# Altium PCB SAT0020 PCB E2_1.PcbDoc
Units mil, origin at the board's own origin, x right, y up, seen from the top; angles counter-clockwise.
Board outline 2000 x 1200 mil, 4 copper layers (Top Layer, GND, VCC, Bottom Layer), stack 90 mil thick; 48 components, 23 nets, 126 pads, 88 vias.
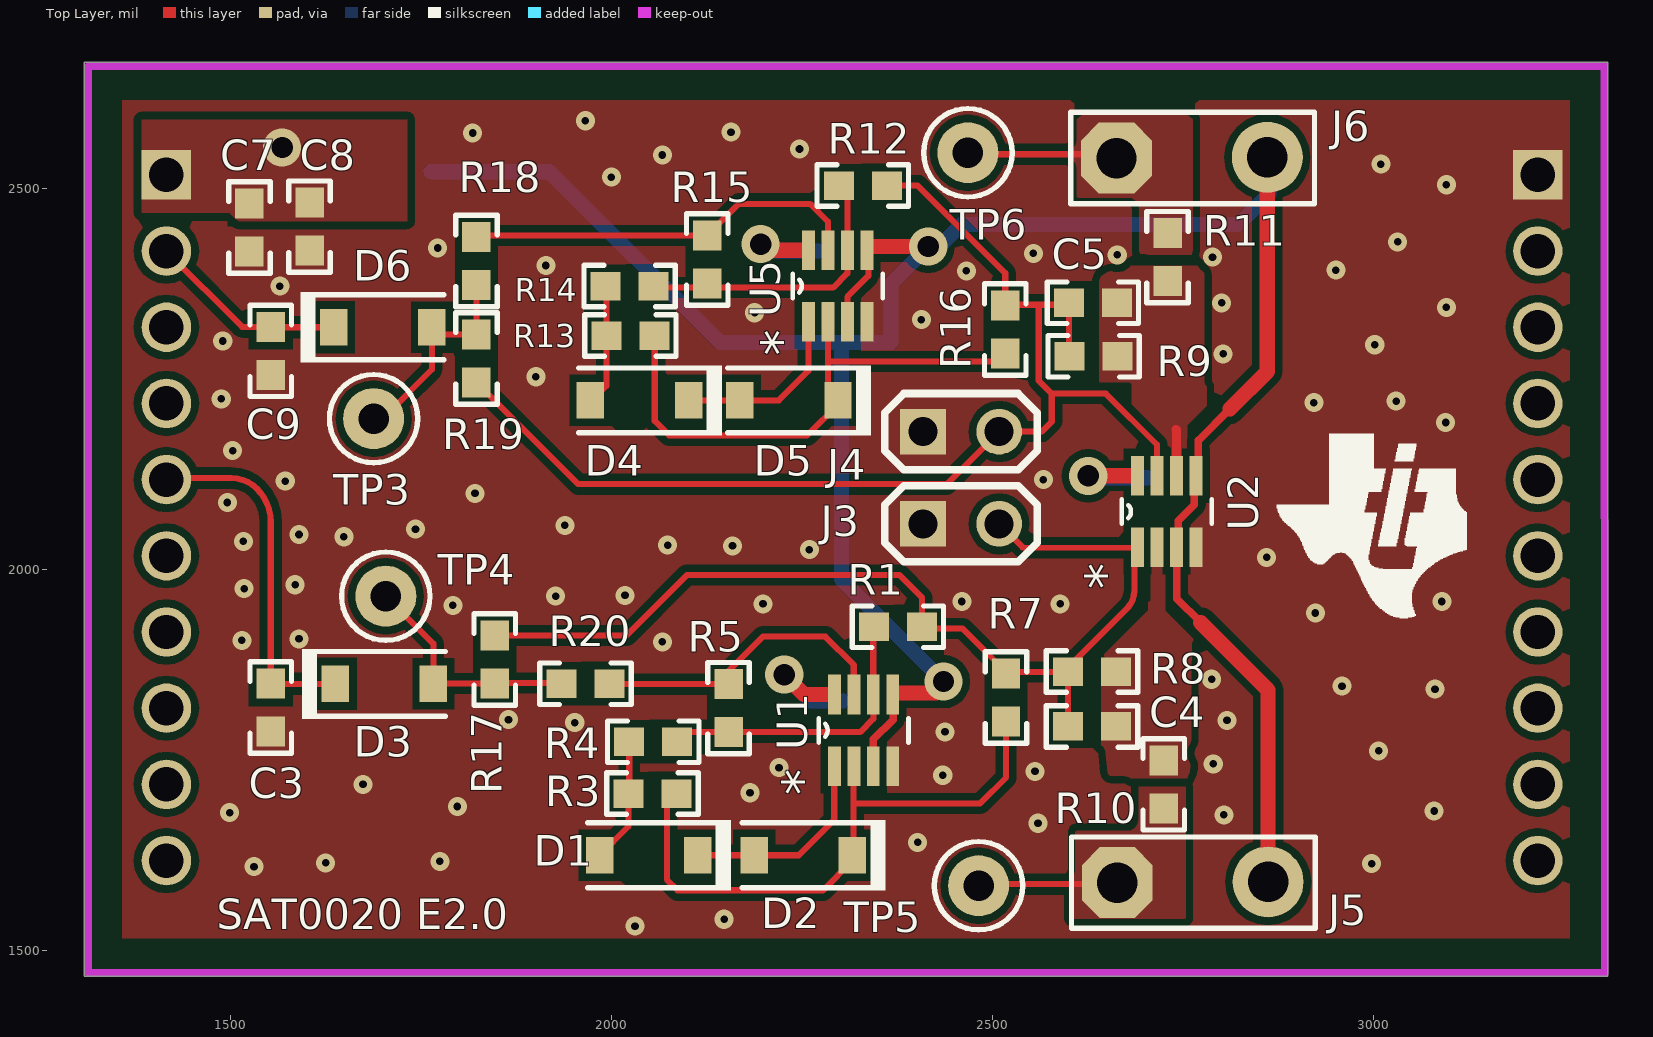
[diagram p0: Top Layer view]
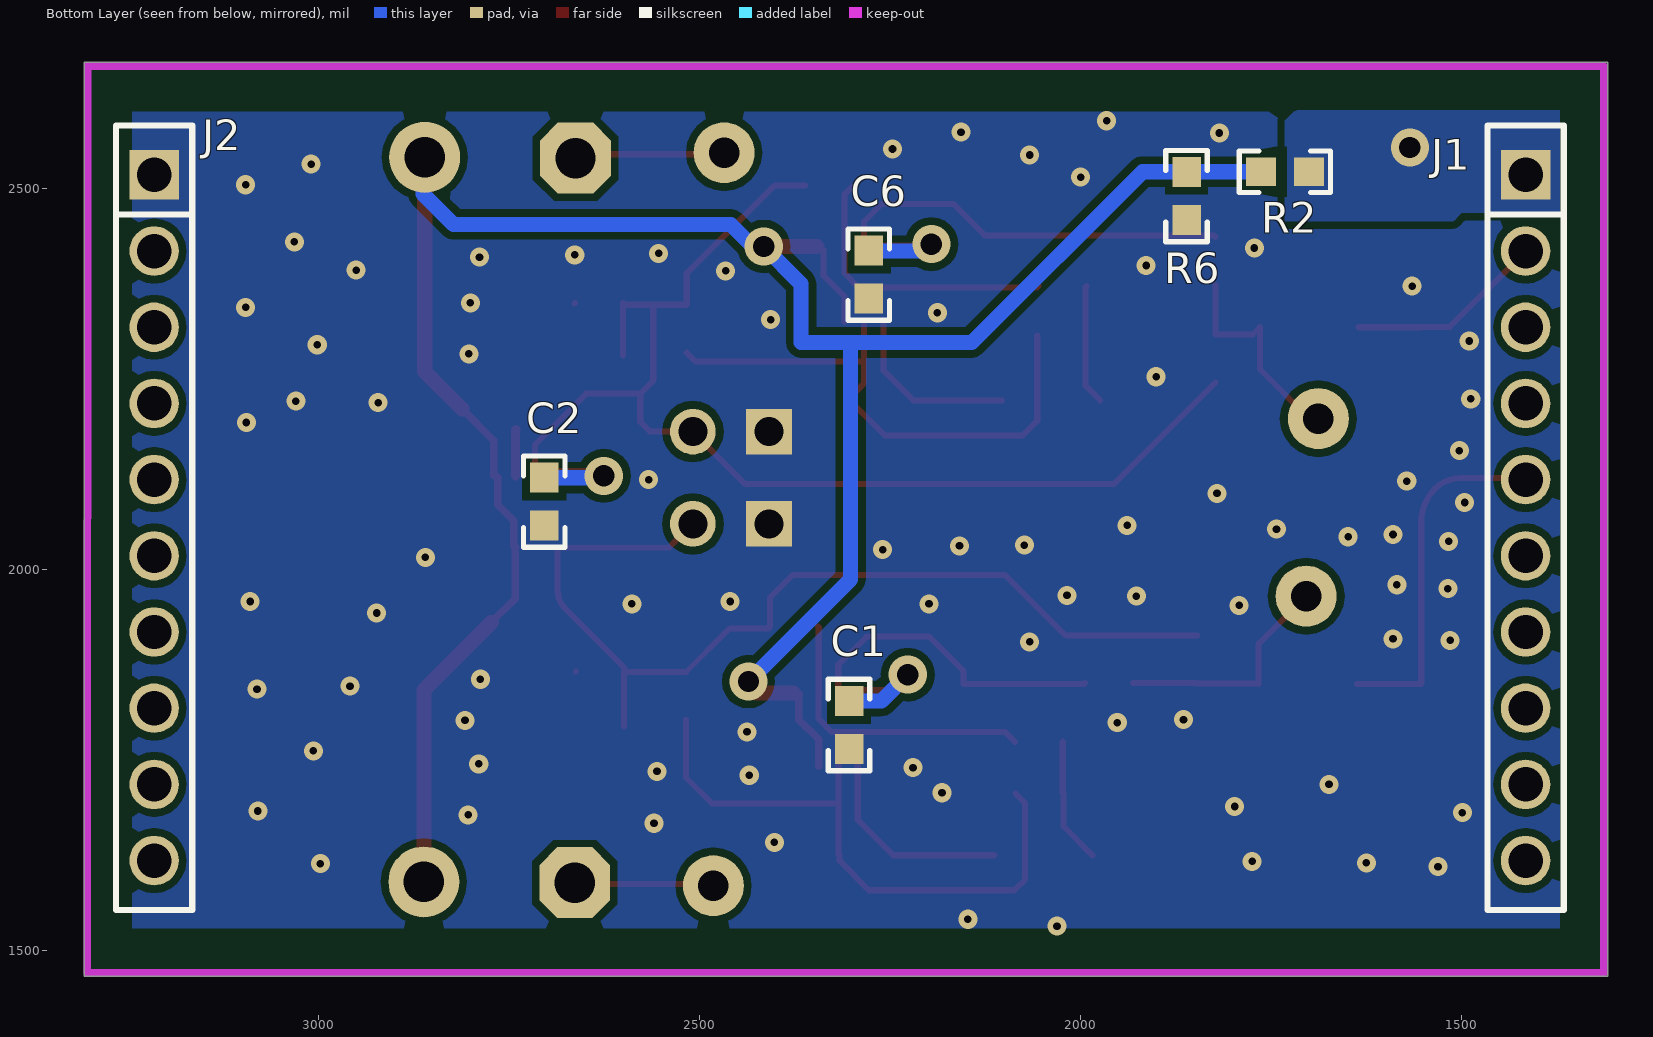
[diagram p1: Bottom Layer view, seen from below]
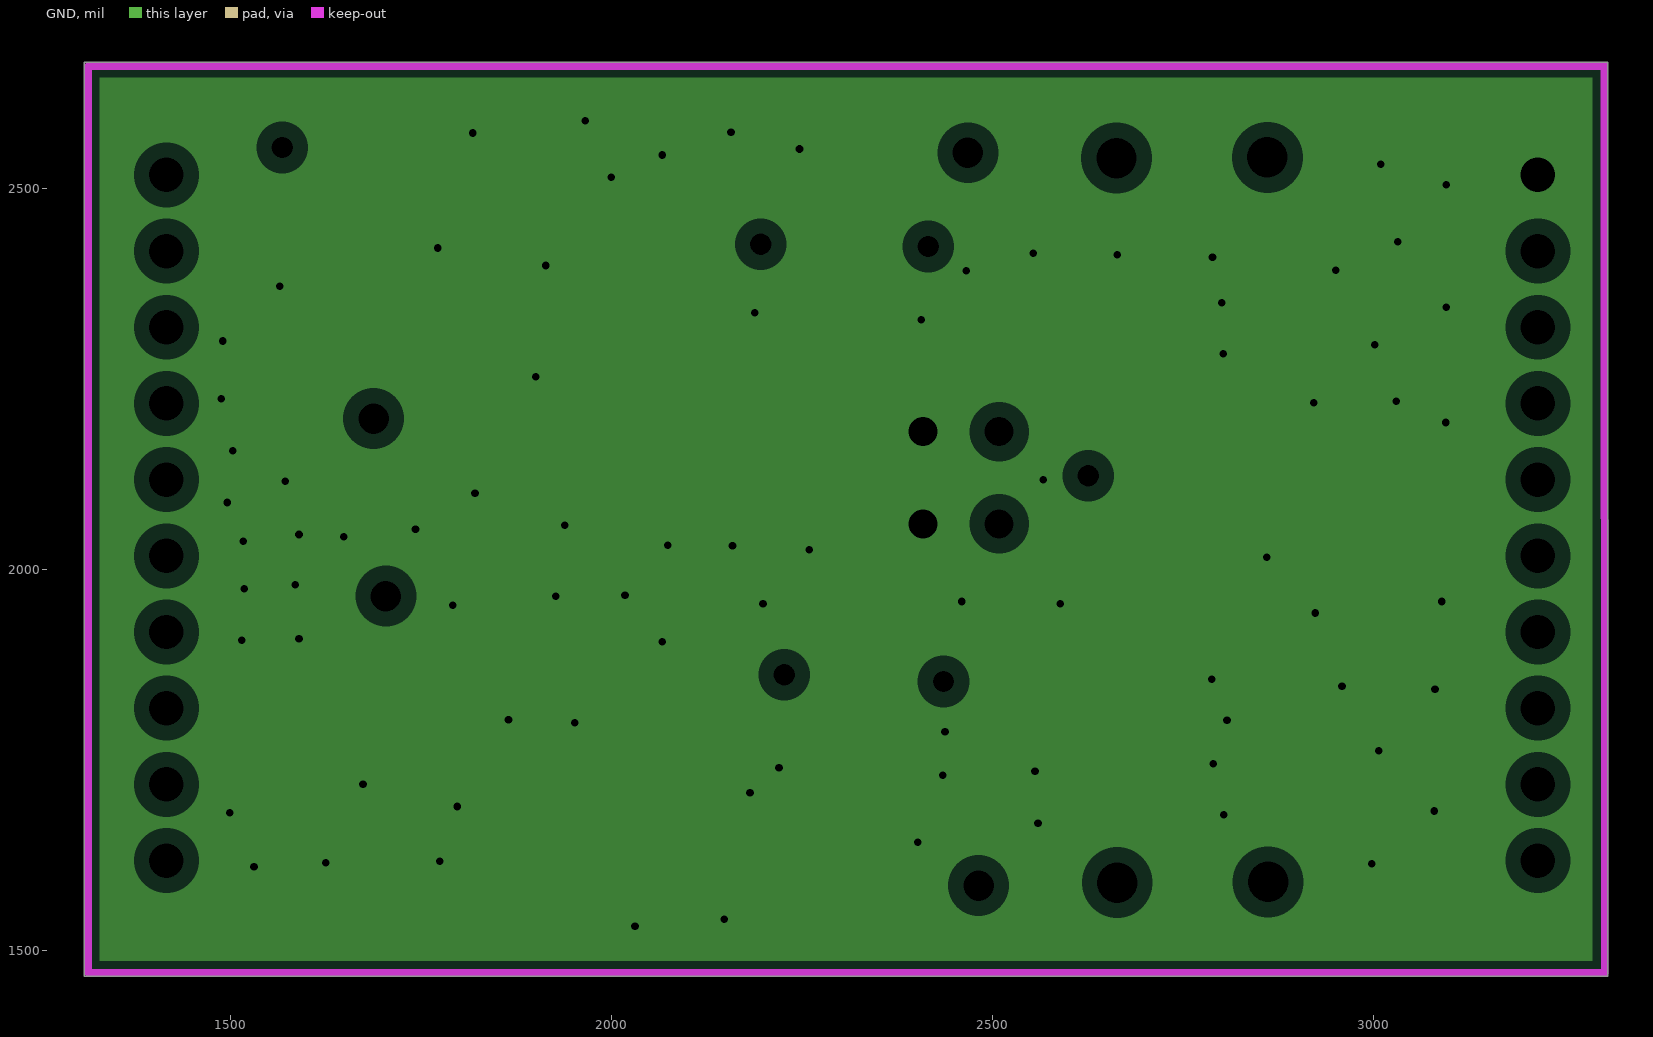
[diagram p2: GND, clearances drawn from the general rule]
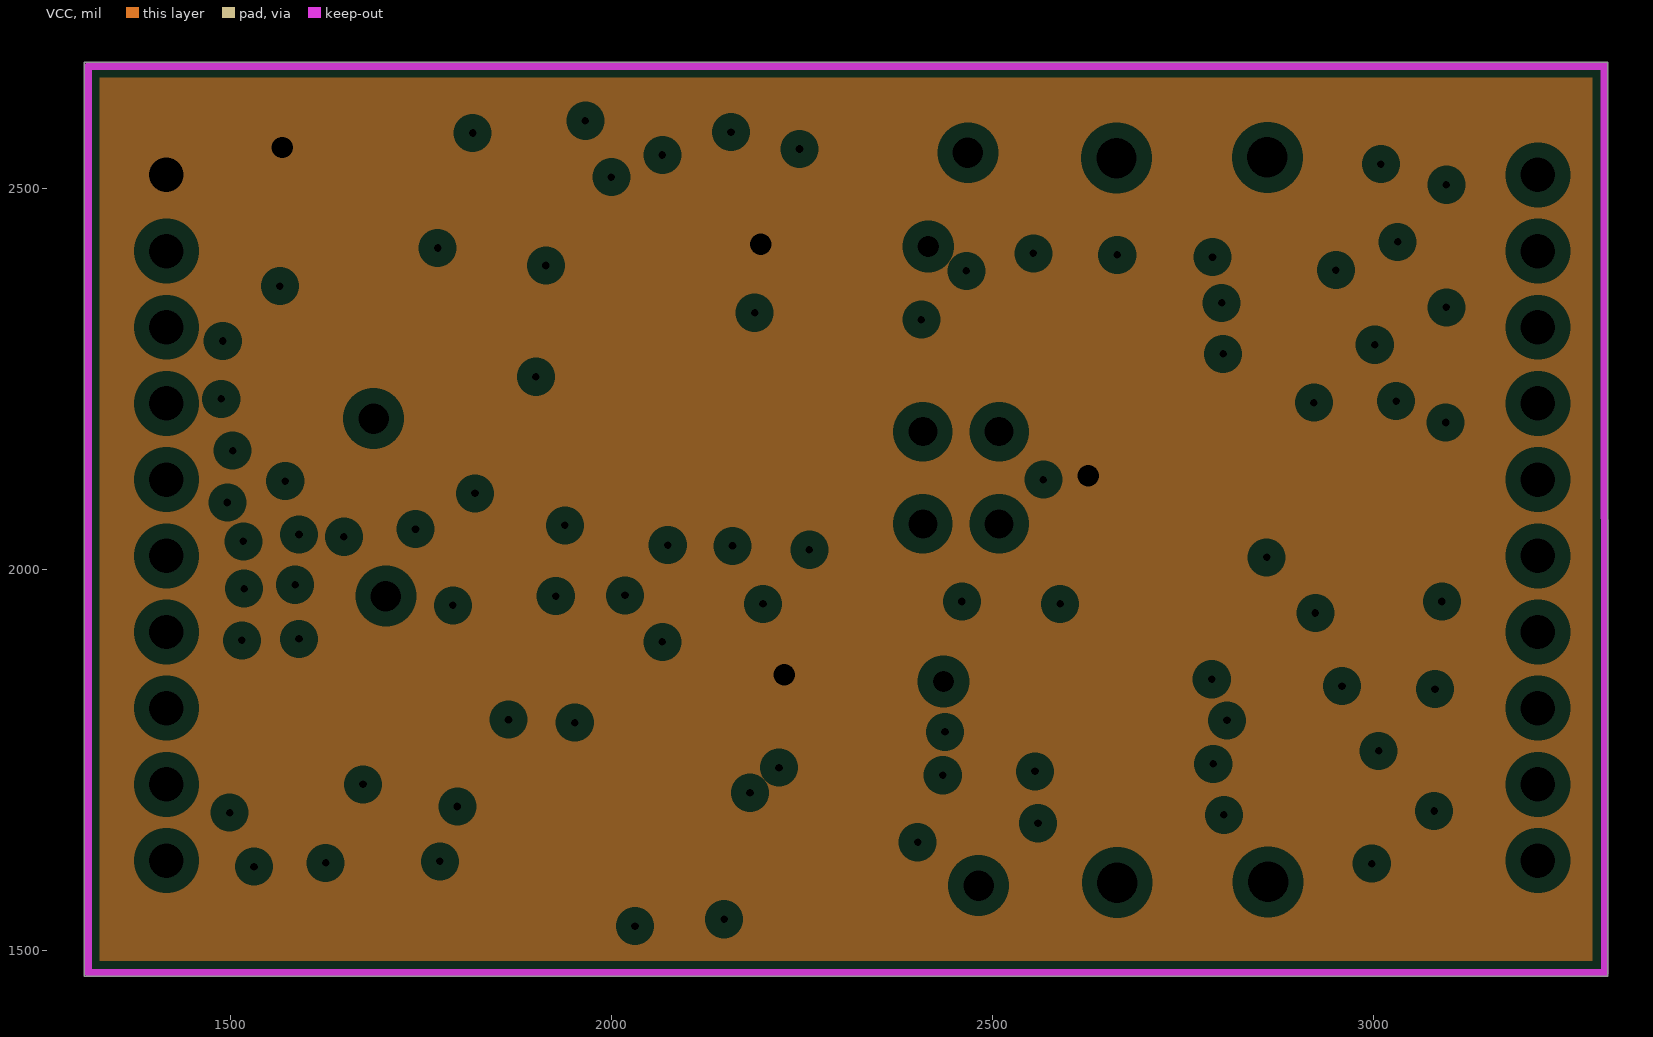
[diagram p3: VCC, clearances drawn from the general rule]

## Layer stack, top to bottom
Top Layer: signal copper 1.4
Dielectric: core 59.2, FR-4, Dk 4.8
GND: plane copper 1.4, net GND
Dielectric: prepreg 12.6, FR-4, Dk 4.8
VCC: plane copper 1.4, net VCC
Dielectric: core 12.6, FR-4, Dk 4.8
Bottom Layer: signal copper 1.4

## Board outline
1308,1466 3308,1466 3308,2666 1308,2666

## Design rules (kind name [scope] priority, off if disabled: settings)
AcuteAngle [All] p1: minimum=4.50000000000000E+0001 checktracksonly=FALSE
AssemblyTestPointUsage [All] p1: valid=2
Clearance [All] p1: gap=10
Clearance Clearance_BoardEdge_MountingHoles [OnCopper and InComponentClass('Mounting Holes') vs IsKeepOut] p2: gap=20
Clearance Clearance_BoardEdge_Poly [OnCopper and InPoly vs IsKeepOut] p3: gap=20
Clearance Clearance_BoardEdge [OnCopper and Not InComponentClass('Logo') and not InComponentClass('FiducialMark') and not InRegion(1000,500,4000,800) vs IsKeepOut] p4: gap=20
Clearance U1 [InComponent('U1')] p5: gap=8
Clearance U2 [InComponent('U2')] p6: gap=8
Clearance U5 [InComponent('U5')] p7: gap=8
ComponentClearance ComponentClearance_Logo [InComponentClass(Logo)] p1 off: gap=50 collisioncheckmode=3 verticalgap=10 showdistances=FALSE
ComponentClearance ComponentClearance_ScrewToNut [(HasFootprint('NY PMS 440 0025 PH')) vs (HasFootprint('Keystone_1902C'))] p2 off: gap=5 collisioncheckmode=3 verticalgap=10 showdistances=FALSE
ComponentClearance ComponentClearance_MountingHoles [InComponentClass('Mounting Holes')] p3 off: gap=250 collisioncheckmode=3 verticalgap=100000 showdistances=FALSE
ComponentClearance ComponentClearance_SmallPassives [HasFootprint('0201*') or HasFootprint('0402*') or HasFootprint('0508') or HasFootprint('0603*') or HasFootprint('0612') or HasFootprint('0805*') or HasFootprint('0815*') or HasFootprint('0830*') or HasFootprint('1206*') or HasFootprint('1210*') or HasFootprint('1808*') or HasFootprint('1812*') or HasFootprint('1825*') or HasFootprint('2010*') or HasFootprint('2220*') or HasFootprint('2225*') or HasFootprint('2512*') or HasFootprint('2728*') or HasFootprint('3518*') vs HasFootprint('0201*') or HasFootprint('0402*') or HasFootprint('0508') or HasFootprint('0603*') or HasFootprint('0612') or HasFootprint('0805*') or HasFootprint('0815*') or HasFootprint('0830*') or HasFootprint('1206*') or HasFootprint('1210*') or HasFootprint('1808*') or HasFootprint('1812*') or HasFootprint('1825*') or HasFootprint('2010*') or HasFootprint('2220*') or HasFootprint('2225*') or HasFootprint('2512*') or HasFootprint('2728*') or HasFootprint('3518*')] p4 off: gap=20 collisioncheckmode=3 verticalgap=10 showdistances=FALSE
ComponentClearance ComponentClearance_THtoSMT [IsThruComponent vs IsSMTComponent] p5 off: gap=100 collisioncheckmode=3 verticalgap=100000 showdistances=FALSE
ComponentClearance ComponentClearance_THtoTH [IsThruComponent vs IsThruComponent] p6 off: gap=118.11 collisioncheckmode=3 verticalgap=100000 showdistances=FALSE
ComponentClearance [All] p7: gap=5 collisioncheckmode=3 verticalgap=10 showdistances=FALSE
DiffPairsRouting [All] p1: maxlimit=100 minlimit=10 mostfreqgap=10 maxuncoupledlength=1000
FabricationTestPointUsage TestPointUsage [All] p1: valid=2 allowmultiple=FALSE
FabricationTestpoint Testpoint [All] p1: side=3 testpointundercomponent=TRUE minsize=40 maxsize=100 preferedsize=60 minholesize=0 maxholesize=40 preferedholesize=32 testpointgrid=1 allowsidetop=TRUE allowsidebottom=TRUE usegrid=TRUE gridtolerance=0.01
FanoutControl Fanout_LCC [IsLCC] p1: bgadir=Out bgaviamode=Centered fanoutstyle=Auto fanoutdirection=Alternating viagrid=1 // Fanout_LCC (Default Rule)
FanoutControl Fanout_BGA [IsBGA] p2: bgadir=Out bgaviamode=Centered fanoutstyle=Auto fanoutdirection=Alternating viagrid=1 // Fanout_BGA (Default Rule)
FanoutControl Fanout_Default [All] p4: bgadir=Out bgaviamode=Centered fanoutstyle=Auto fanoutdirection=Alternating viagrid=1 // Fanout_Default (Default Rule)
FanoutControl Fanout_Small [(CompPinCount < 5)] p5: bgadir=Out bgaviamode=Centered fanoutstyle=Auto fanoutdirection=OutThenIn viagrid=1 // Fanout_Small (Default Rule)
HoleSize [All] p1: absolutevalues=TRUE maxlimit=550 minlimit=5 maxpercent=80.000 minpercent=20.000
MinimumAnnularRing [All] p1: minimumring=8
MinimumSolderMaskSliver MinimumSolderMaskSliver_Logo [InComponentClass('Logo') vs InComponentClass('Logo')] p1: minsoldermaskwidth=0.7
MinimumSolderMaskSliver [All] p2: minsoldermaskwidth=5
PlaneClearance [All] p1: clearance=20
PlaneConnect [All] p1: planeconnectstyle=Direct reliefexpansion=10 reliefentries=4 reliefconductorwidth=10 reliefairgap=10
PolygonConnect [All] p1: connectstyle=Direct reliefconductorwidth=10 reliefentries=4 polygonreliefangle="90 Angle" airgapwidth=10
RoutingVias [All] p1: holewidth=10 width=25 viastyle="Through Hole" minholewidth=5 minwidth=20 maxholewidth=100 maxwidth=150
SMDToCorner [All] p1: distance=30000
SilkToSilkClearance [All] p1: silktosilkclearance=5
SilkscreenOverComponentPads [All] p1: minsilkscreentomaskgap=5
SolderMaskExpansion [All] p1: expansion=3
Width [All] p1: maxlimit=100 minlimit=6 preferedwidth=10 checkconnectedcopper=TRUE
13 further rules are at their usual default settings.

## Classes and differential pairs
component class Hardware_ANSI-B: !PCB

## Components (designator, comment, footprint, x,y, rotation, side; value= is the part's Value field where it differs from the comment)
C1 "06033C104KAT2A" 0603 2304,1796 r90 bottom
C2 "06033C104KAT2A" 0603 2704,2089 r270 bottom
C3 "C1608X5R0J105K" 0603 1553,1819 r270 top
C4 "C0603C681K5RACTU" 0603 2631,1794 r0 top
C5 "C0603C681K5RACTU" 0603 2632,2350 r0 top
C6 "06033C104KAT2A" 0603 2278,2387 r90 bottom
C7 "GRM188R60J106ME47D" 0603 1525,2449 r270 top
C8 "06033C104KAT2A" 0603 1604,2450 r90 top
C9 "C1608X5R0J105K" 0603 1553,2287 r270 top
D1 "1N4148W-7-F" SOD-123 2049,1625 r180 top
D2 "1N4148W-7-F" SOD-123 2252,1625 r180 top
D3 "1N4148W-7-F" SOD-123 1702,1850 r0 top
D4 "1N4148W-7-F" SOD-123 2037,2222 r180 top
D5 "1N4148W-7-F" SOD-123 2233,2222 r180 top
D6 "1N4148W-7-F" SOD-123 1700,2318 r0 top
J1 "SSW-110-23-F-S" CONN_SSW-110-23-F-S 1416,2518 r90 bottom
J2 "SSW-110-23-F-S" CONN_SSW-110-23-F-S 3216,2518 r90 bottom
J3 "HEADER_1X2" HDR100_1X2 2409,2060 r0 top
J4 "HEADER_1X2" HDR100_1X2 2409,2181 r0 top
J5 "DT_Sensor" DT_Sensor 2824,1449 r0 top
J6 "DT_Sensor" DT_Sensor 2823,2400 r0 top
R1 "CRCW0603100KFKEA" 0603 2376,1925 r180 top
R2 "CRCW060310K0JNEA" 0603 1732,2522 r180 bottom
R3 "CRCW0603100KFKEA" 0603 2054,1706 r180 top
R4 "CRCW060351K0JNEA" 0603 2055,1774 r0 top
R5 "CRCW0603100KFKEA" 0603 2154,1818 r90 top
R6 "CRCW060310K0JNEA" 0603 1861,2490 r90 bottom
R7 "CRCW0603100KFKEA" 0603 2518,1832 r270 top
R8 "CRCW0603200MJPEAHR" 0603 2631,1866 r180 top
R9 "CRCW0603200MJPEAHR" 0603 2633,2280 r180 top
R10 "CRCW060310K0JNEA" 0603 2725,1718 r270 top
R11 "CRCW060310K0JNEA" 0603 2730,2410 r270 top
R12 "CRCW0603100KFKEA" 0603 2330,2504 r180 top
R13 "CRCW0603100KFKEA" 0603 2025,2307 r180 top
R14 "CRCW060351K0JNEA" 0603 2024,2372 r0 top
R15 "CRCW0603100KFKEA" 0603 2126,2407 r90 top
R16 "CRCW0603100KFKEA" 0603 2517,2315 r270 top
R17 "CRCW06030000Z0EA" 0603 1847,1882 r270 top
R18 "CRCW06030000Z0EA" 0603 1823,2405 r90 top
R19 "CRCW06030000Z0EA" 0603 1823,2277 r90 top
R20 "CRCW06030000Z0EA" 0603 1966,1850 r0 top
TP3 "5002" Keystone5002 1688,2198 r90 top
TP4 "5002" Keystone5002 1704,1965 r90 top
TP5 "5002" Keystone5002 2482,1585 r0 top
TP6 "5002" Keystone5002 2468,2547 r0 top
U1 "OPA2337_DCN_8" DCN8 2331,1789 r90 top
U2 "OPA2337_DCN_8" DCN8 2729,2076 r90 top
U5 "OPA2337_DCN_8" DCN8 2297,2372 r90 top

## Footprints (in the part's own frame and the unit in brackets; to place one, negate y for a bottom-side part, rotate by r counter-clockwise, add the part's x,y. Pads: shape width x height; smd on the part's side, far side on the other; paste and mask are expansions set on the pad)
0603 [mm] "0603 from SM-752 data"
  rect 1x0.95 smd: 1(-0.8,0) 2(0.8,0)
  silkscreen extent -1.52,-0.69 1.52,0.69, body extent -0.87,-0.47 0.87,0.47, height 0.85
CONN_SSW-110-23-F-S [mm] "SAMTEC"
  rect 1.65x1.65 hole 1.15: 1(0,0)
  round 1.65 hole 1.15: 2(-2.54,0) 3(-5.08,0) 4(-7.62,0) 5(-10.16,0) 6(-12.7,0) 7(-15.24,0) 8(-17.78,0) 9(-20.32,0) 10(-22.86,0)
  silkscreen extent -24.51,-1.27 1.65,1.27, body extent -24.43,-1.27 1.57,1.27, height 8.59
DCN8 [mil]
  rect 52x17 smd: 1(-47,38.39) 2(-47,12.8) 3(-47,-12.8) 4(-47,-38.39) 5(47,-38.39) 6(47,-12.8) 7(47,12.8) 8(47,38.39)
  silkscreen extent -16,-59 16,59
DT_Sensor [mil]
  oct 93x93 hole 53: 1(-160,140)
  round 93 hole 53: 2(38,141)
  silkscreen extent -220,80 100,200
HDR100_1X2 [mil]
  rect 60x60 hole 38: 1(0,0)
  round 60 hole 38: 2(100,0)
  silkscreen extent -50,-50 150,50
Keystone5002 [mil] "For Keystone 500x miniature loop terminals"
  round 80 hole 40: 1(0,0)
  silkscreen extent -58,-58 58,58, body extent -49,-49 49,49, height 182
SOD-123 [mm] "On Semi recommended land pattern"
  rect 0.915x1.22 smd: 1(-1.637,0) 2(1.637,0)
  silkscreen extent -2.74,-1.17 2.03,1.17, body extent -1.93,-0.9 1.93,0.9, height 1.35

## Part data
C1 C2 C6 C8: "CAP, CERM, 0.1uF, 25V, +/-10%, X7R, 0603"
C3 C9: "CAP, CERM, 1uF, 6.3V, +/-10%, X5R, 0603"
C4 C5: "CAP, CERM, 680pF, 50V, +/-10%, X7R, 0603"
C7: "CAP, CERM, 10uF, 6.3V, +/-20%, X5R, 0603"
D1 D2 D3 D4 D5 D6: "Diode, Ultrafast, 100V, 0.15A, SOD-123"
J1 J2: "Connector, Receptacle, 100mil, 10x1, Gold plated, TH"
J3 J4: "Header, Male 2-pin, 100mil spacing,"
J5 J6: library part Component_1
R1 R3 R5 R7 R12 R13 R15 R16: "RES, 100k ohm, 1%, 0.1W, 0603"
R2 R6 R10 R11: "RES, 10k ohm, 5%, 0.1W, 0603"
R4 R14: "RES, 51k ohm, 5%, 0.1W, 0603"
R8 R9: library part CRCW0603200KJNEA, "RES, 200M ohm, 5%, 0.1W, 0603"
R17 R18 R19 R20: "RES, 0 ohm, 5%, 0.1W, 0603"
TP3 TP4 TP5 TP6: "Test Point, TH, Miniature, White"
U1 U2 U5: "Imported"

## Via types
v1: diameter 25, hole 10, Top Layer to Bottom Layer, 82 vias
v2: diameter 50, hole 28, Top Layer to Bottom Layer, 6 vias

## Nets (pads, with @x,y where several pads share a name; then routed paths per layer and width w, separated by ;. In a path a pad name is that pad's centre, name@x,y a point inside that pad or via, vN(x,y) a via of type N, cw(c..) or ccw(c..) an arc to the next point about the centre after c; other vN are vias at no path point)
GND: C1.1 C2.2 C3.2 C6.1 C7.2 C8.1 C9.2 J2.1 J3.1 J4.1 R6.1 U1.4 U2.4 U5.4
  other v1: 2031,1532 2148,1541 1531,1610 2998,1614 1625,1615 1775,1617 2402,1642 2560,1667 2804,1678 1499,1681 3080,1683 1798,1689 2182,1707 1674,1718 2435,1730 2556,1735 2220,1740 2790,1745 3007,1762 2438,1787 1952,1799 2808,1802 1865,1803 3081,1843 2959,1847 2788,1856 2067,1905 1515,1907 1590,1909 2924,1943 1792,1953 2199,1955 2589,1955 2460,1958 3090,1958 1927,1965 2018,1966 1518,1975 1585,1980 2860,2016 2260,2026 2159,2031 2074,2032 1517,2037 1649,2043 1590,2046 1743,2053 1939,2058 1496,2088 1821,2100 1572,2116 2567,2118 1503,2156 3095,2193 2922,2219 3030,2221 1488,2224 1901,2253 2803,2283 3002,2295 1490,2300 2407,2328 2188,2337 3096,2344 2801,2350 1565,2372 2466,2392 2951,2393 1914,2399 2789,2410 2664,2413 2554,2415 1772,2422 3032,2430 3096,2505 2000,2515 3010,2532 2067,2544 2247,2552 1818,2573 2157,2574 1966,2589
NetC4_1: C4.1 J3.2 R1.1 R7.1 R8.2 R17.1 U2.1 | length 1322
  Top Layer w8: R17.1 2019.95,1913.5 2099.19,1992.74 2378.26,1992.74 2407.5,1963.5 R1.1 2410,1922.5 2461,1922.5 2518,1865.5 2598,1865.5 R8.2@2598.5,1866 ; J3.2 2540,2029 2686.61,2028 2686.61,1970.09 ; C4.1 R8.2 R8.2@2598.5,1866 ; 2677.89,1950.41 ccw(c2658.3,1970) 2686,1970 ; 2679.5,1951.5 2598.5,1870.5 R8.2@2598.5,1866
NetC4_2: C4.2 R8.1 R10.1 U2.2 | length 0
NetC5_1: C5.1 J4.2 R9.2 R12.1 R16.1 R19.1 U2.7 | length 1609.8
  Top Layer w8: R19.1 1956.5,2112 2440,2112 J4.2 2565,2181 2578,2194 2578,2231 ; R12.1 2402,2504 2517,2389 2517,2347.5 2561,2347.5 ; R9.2@2600.5,2281 C5.1 2598,2347.5 2561,2347.5 ; U2.7 2716.2,2163.8 2649,2231 2578,2231 ; 2561,2347.5 2561,2248 2578,2231
NetC5_2: C5.2 R9.1 R11.2 U2.6 | length 62.7
  Top Layer w8: C5.2 C5.2@2664.5,2349
  Top Layer w12: 2741,2184 2741.8,2183.2 U2.6
NetD1_1: D1.1 D2.2 U1.1 | length 268.8
  Top Layer w8: D1.1 D2.2 2246,1625 2292.61,1671.61 U1.1
NetD1_2: D1.2 R3.2 R4.1 | length 165.1
  Top Layer w8: D1.2 2022.5,1662.97 R3.2 2023.5,1707 R4.1
NetD2_1: D2.1 R3.1 R7.2 U1.2 | length 798.5
  Top Layer w8: R3.1 2073,1693.5 2073,1593 2087,1579 2278,1579 2316.47,1617.47 D2.1 2318,1626.53 2318,1694.47 ; U1.2@2318,1741.8 2318,1694.47 ; R7.2@2518,1802.5 2518,1727 2484,1693 2319.47,1693 2318,1694.47
NetD3_2: D3.2 R17.2 R20.1 TP4.1 | length 306.3
  Top Layer w8: TP4.1 1766.47,1902.53 D3.2 1766.97,1850.5 R17.2 1847.5,1851 R20.1@1931.5,1851
NetD4_1: D4.1 D5.2 U5.1 | length 235.5
  Top Layer w8: D4.1@2103.47,2222 2170.53,2222 2220,2222 2258.61,2260.61 U5.1
NetD4_2: D4.2 R13.2 R14.1 | length 158.3
  Top Layer w8: D4.2@1974.53,2222 1993.5,2240.97 R13.2 1993.5,2371 R14.1
NetD5_1: D5.1 R13.1 R16.2 U5.2 | length 733.5
  Top Layer w8: R13.1 2057,2306.5 2057,2195 2076,2176 2257,2176 2299.47,2218.47 2299.47,2222 2303,2225.53 2284.2,2244.33 2284.2,2273 ; U5.2 2284.2,2273 ; R16.2@2517,2284.5 2505.5,2273 2284.2,2273
NetD6_2: D6.2 R18.1 R19.2 TP3.1 | length 286.1
  Top Layer w8: TP3.1 1699.94,2198 1764.47,2262.53 D6.2 1773.97,2308.5 R19.2 R18.1
NetJ5_1: J5.1 R10.2 TP5.1 | length 180.1
  Top Layer w8: TP5.1@2482,1587 2659.99,1587 J5.1@2661.5,1588.5
NetJ6_1: J6.1 R11.1 TP6.1 | length 172.1
  Top Layer w8: TP6.1@2495,2545 2665,2545 J6.1@2663.5,2543.5
NetR1_2: R1.2 R4.2 R5.1 U1.6 | length 391.4
  Top Layer w8: R4.2 2099,1786.5 2326.63,1786.5 2344,1803.87 2344,1835.8 U1.6 2343.8,1924.29 R1.2
NetR5_2: R5.2 R20.2 U1.7 | length 414.7
  Top Layer w8: R20.2@1994.5,1851 1996,1849.5 R5.2 2154,1867 2199,1912 2281,1912 2318.2,1874.8 U1.7
NetR12_2: R12.2 R14.2 R15.1 U5.6 | length 382.8
  Top Layer w8: R14.2 2057.5,2370 2291,2370 2309.8,2388.8 U5.6 2309.8,2492.71 R12.2
NetR15_2: R15.2 R18.2 U5.7 | length 526.6
  Top Layer w8: R18.2 1825,2438.5 R15.2 2167.5,2480 2261,2480 2284.2,2456.8 U5.7
VCC: C1.2 C2.1 C6.2 C7.1 C8.2 J1.1 R2.2 U1.8 U2.8 U5.8 | length 450.7
  Top Layer w20: v2(2196,2427) 2204,2419 U5.8@2255.7,2419 ; v2(2227,1862) 2253,1836 U1.8@2289.7,1836 ; v2(2626,2123) U2.8@2687.7,2123
  Bottom Layer w20: v2@2196,2418 2277.5,2418 C6.2 ; v2(2227,1862) 2261.5,1827.5 C1.2 ; v2(2626,2123) 2628.5,2120.5 C2.1
  other v2: 1568,2554
VCCDIV2: J5.2 J6.2 R2.1 R6.2 U1.3 U1.5 U2.3 U2.5 U5.3 U5.5 | length 3275.4
  Top Layer w8: U5.3 2309.8,2357.8 2337.3,2385.3 U5.5@2337.3,2419
  Top Layer w10: U1.3 2344,1742.2 2344,1777 2370,1803 2370,1835.39 U1.5 ; U2.5 2765.3,2120.91 2765.3,2085.3 2743.89,2063.89 2743.89,2031.09 U2.3 2742.2,2028.59 2742.2,1961.8 2773.5,1930.5 ; U2.5@2770.3,2123 2770.3,2169.3 2812,2211
  Top Layer w20: 2346,2424 v2(2416,2424) ; U1.5@2376.89,1838 v2@2426.5,1838 ; v2@2425,1842 v2(2436,1853) ; 2773.5,1930.5 2862,1842 J5.2 ; 2812,2211 2861,2260 J6.2
  Bottom Layer w20: R2.1 1919,2522 2143,2298 2367,2298 2367,2375 v2(2416,2424) v2@2416,2409.75 ; 2302,2297 2302,1987 v2(2436,1853) ; v2@2423.12,2416.88 2459.25,2453 2823,2453 2863,2493 J6.2@2863,2546
"VOUT 1": C3.1 D3.1 J1.5 | length 476.8
  Top Layer w8: J1.5@1407,2120 1501.2,2120 cw(c1501.2,2072.2) 1535,2106 cw(c1491.54,2062.54) 1553,2062.54 C3.1 1553.5,1850 D3.1
"VOUT 2": C9.1 D6.1 J1.2 | length 261
  Top Layer w8: J1.2 1515.5,2318.5 C9.1 1553.5,2318 D6.1
pads on no net: J1.3 J1.4 J1.6 J1.7 J1.8 J1.9 J1.10 J2.2 J2.3 J2.4 J2.5 J2.6 J2.7 J2.8 J2.9 J2.10

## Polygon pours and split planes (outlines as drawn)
GND on Bottom Layer "GND-BL" (solid, remove dead copper, pour order 24): 1371.25,2602.75 1371.25,1529.25 3244.75,1529.25 3244.75,2600.85 1373.15,2600.85 1371.25,2602.75
VCC on Bottom Layer "Vcc-In-BL" (solid, pour order 22): 1371.25,2602.75 1371.25,2469.25 1370,2468 1498.51,2468 1499.77,2468 1510.77,2457 1732,2457 1732,2602.75 1371.25,2602.75
GND on Top Layer "GND-TL" (solid, remove dead copper, pour order 38): 3258,2616 3258,1516 1358,1516 1358,2616
NetC5_2 on Top Layer "Amp-In-2" (solid, pour order 13): 2640.5,2399.5 2640.5,2247.5 2639,2246 2680,2246 2683,2243 2683,2212.99 2686,2209.99 2727.51,2168.48 2729.1,2166.88 2729.1,2099.18 2754.4,2099.18 2755.29,2098.29 2756,2099 2756,2189.6 2781.28,2214.88 2781.28,2218.02 2781.28,2399.72 2780.55,2399 2640,2399
NetJ6_1 on Top Layer "Sens-IN-2" (solid, pour order 11): 2603,2600 2771,2600 2771,2409 2685,2409 2685,2480 2603,2480 2603,2600
VCC on Top Layer "Vcc-TL" (solid, pour order 16): 1371.25,2602.75 1371.25,2468.75 1372.09,2468 1492.43,2468 1498.51,2468 1510.77,2457 1732,2457 1732,2605 1373.77,2605 1371.25,2602.75
NetC4_2 on Top Layer "IN- 1" (solid, pour order 28): 2708,2053 2708,1960 2705,1957 2705,1946.7 2643,1884.7 2643,1729 2646,1726 2762,1726 2762,1904.19 2764,1906.19 2764,1909 2727,1946 2727,2048 2721,2054
NetJ5_1 on Top Layer "Sens-IN" (solid, pour order 34): 2604,1526 2762,1526 2762,1718 2684,1718 2684,1665 2601,1665 2604,1662 2604,1526
GND on GND (split plane): 3287.9,1486.1 1328.1,1486.1 1328.1,2645.9 3287.9,2645.9
VCC on VCC (split plane): 3287.9,1486.1 1328.1,1486.1 1328.1,2645.9 3287.9,2645.9

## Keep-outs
Keep-Out Layer:
  lines w10: 3302.99,2660.78 1313.69,2660.78 1313.69,1471 3304,1471 3302.99,2661

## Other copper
Top Layer:
  pour cut-out: 2041.88,1672.3 2053.63,1672.3 2053.63,1584.98 2059.3,1579.3 2024.23,1579.3 2017.54,1585.98 2017.54,1630.62 2018.62,1630.62 2042,1654 2042,1672.18
  pour cut-out: 2012.88,2273.3 2011.4,2271.82 2011.4,2231.47 2005.54,2225.62 2005.54,2182.98 2042.18,2182.98 2042.18,2268.75 2037.63,2273.3
  pour cut-out: 2667.11,2084.03 2667.11,2070 2669.75,2067.37 2722.68,2067.37 2720,2070.05 2720,2085 2719,2084 2670,2084

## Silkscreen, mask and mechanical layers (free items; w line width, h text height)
Top Overlay:
  drawing of 3 lines, arcs and shapes, not listed
  text "SAT0020 E2.0" at 1482,1528 h40

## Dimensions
1308,1466 to 3308,1466 on M2 Board Dimensions
1308,1466 to 1308,2666 on M2 Board Dimensions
